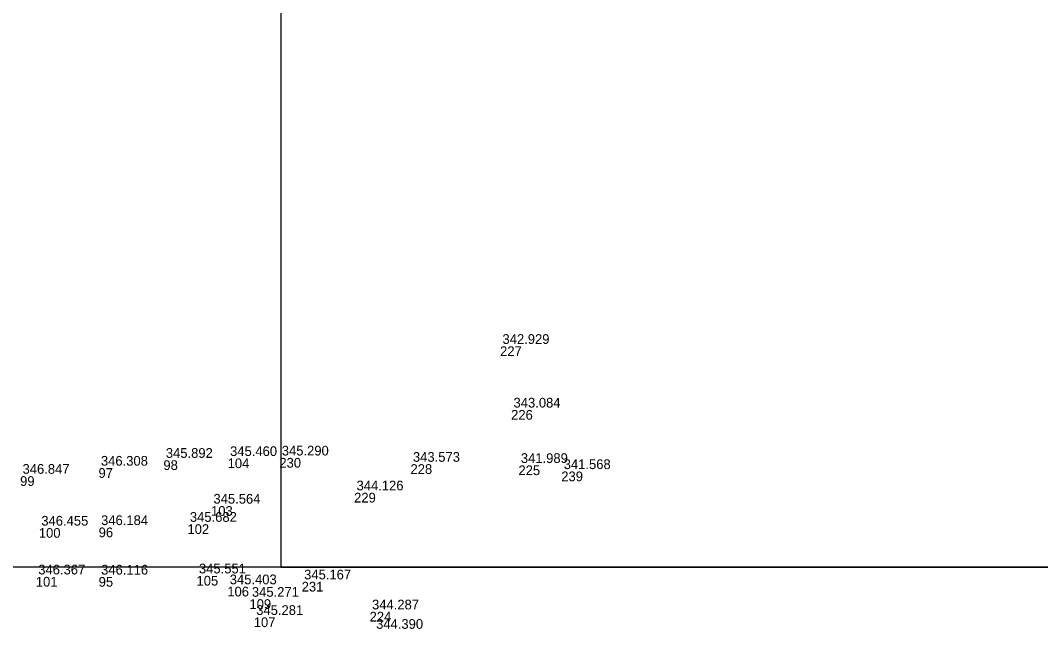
# Model space of a CAD drawing. Extents: x -829398 to -819400, y -1074439 to -1067977.
# Drawn here: x -820132.1 to -820006.2, y -1073007.7 to -1072932.5 of the extents above; entities that cross this region are included whole.
import ezdxf

# ---------------------------------------------------------------- set-up
doc = ezdxf.new("R2010")
doc.units = 0
doc.layers.add('Vrstva 60', color=7, linetype='Continuous')
doc.layers.add('Vrstva 61', color=7, linetype='Continuous')

msp = doc.modelspace()

# ---------------------------------------------------------------- linework, layer by layer
at = {"layer": 'Vrstva 60'}
for p, q in [((-820072.932, -1072972.745), (-820072.932, -1072972.745)), ((-820071.568, -1072980.602), (-820071.568, -1072980.602)), ((-820114.491, -1072986.81), (-820114.491, -1072986.81)), ((-820106.559, -1072986.584), (-820106.559, -1072986.584)), ((-820100.177, -1072986.52), (-820100.177, -1072986.52)), ((-820122.503, -1072987.778), (-820122.503, -1072987.778)), ((-820083.986, -1072987.296), (-820083.986, -1072987.296)), ((-820070.663, -1072987.445), (-820070.663, -1072987.445)), ((-820065.374, -1072988.197), (-820065.374, -1072988.197)), ((-820090.948, -1072990.825), (-820090.948, -1072990.825)), ((-820108.61, -1072992.466), (-820108.61, -1072992.466)), ((-820111.523, -1072994.708), (-820111.523, -1072994.708)), ((-820129.862, -1072995.178), (-820129.862, -1072995.178)), ((-820122.481, -1072995.109), (-820122.481, -1072995.109)), ((-820130.238, -1073001.201), (-820130.238, -1073001.201)), ((-820122.479, -1073001.22), (-820122.479, -1073001.22)), ((-820110.403, -1073001.077), (-820110.403, -1073001.077)), ((-820097.418, -1073001.815), (-820097.418, -1073001.815)), ((-820106.602, -1073002.418), (-820106.602, -1073002.418)), ((-820103.866, -1073003.96), (-820103.866, -1073003.96)), ((-820089.036, -1073005.519), (-820089.036, -1073005.519)), ((-820103.333, -1073006.203), (-820103.333, -1073006.203))]:
    msp.add_line(p, q, dxfattribs=at)
at = {"layer": 'Vrstva 61'}
for points in [[(-819400, -1072500), (-820100, -1072500), (-820100, -1073000), (-819400, -1073000)], [(-819500, -1073000), (-820200, -1073000), (-820200, -1073500), (-819500, -1073500)]]:
    msp.add_lwpolyline(points, close=True, dxfattribs=at)

# ---------------------------------------------------------------- texts
at = {"layer": 'Vrstva 60'}
for s, p in [('227', (-820072.932, -1072973.945)), ('226', (-820071.568, -1072981.802)), ('98', (-820114.491, -1072988.01)), ('104', (-820106.559, -1072987.784)), ('230', (-820100.177, -1072987.72)), ('97', (-820122.503, -1072988.978)), ('228', (-820083.986, -1072988.496)), ('225', (-820070.663, -1072988.645)), ('239', (-820065.374, -1072989.397)), ('99', (-820132.179, -1072989.977)), ('229', (-820090.948, -1072992.025)), ('103', (-820108.61, -1072993.666)), ('102', (-820111.523, -1072995.908)), ('100', (-820129.862, -1072996.378)), ('96', (-820122.481, -1072996.309)), ('101', (-820130.238, -1073002.401)), ('95', (-820122.479, -1073002.42)), ('105', (-820110.403, -1073002.277)), ('231', (-820097.418, -1073003.015)), ('106', (-820106.602, -1073003.618)), ('109', (-820103.866, -1073005.16)), ('224', (-820089.036, -1073006.719)), ('107', (-820103.333, -1073007.403))]:
    msp.add_text(s, height=1.2, dxfattribs=at).set_placement(p)
at = {"layer": 'Vrstva 61'}
for s, p in [('342.929', (-820072.632, -1072972.445)), ('343.084', (-820071.268, -1072980.302)), ('345.892', (-820114.191, -1072986.51)), ('345.460', (-820106.259, -1072986.284)), ('345.290', (-820099.877, -1072986.22)), ('343.573', (-820083.686, -1072986.996)), ('346.308', (-820122.203, -1072987.478)), ('341.989', (-820070.363, -1072987.145)), ('341.568', (-820065.074, -1072987.897)), ('346.847', (-820131.879, -1072988.477)), ('344.126', (-820090.648, -1072990.525)), ('345.564', (-820108.31, -1072992.166)), ('345.682', (-820111.223, -1072994.408)), ('346.455', (-820129.562, -1072994.878)), ('346.184', (-820122.181, -1072994.809)), ('346.367', (-820129.938, -1073000.901)), ('346.116', (-820122.179, -1073000.92)), ('345.551', (-820110.103, -1073000.777)), ('345.403', (-820106.302, -1073002.118)), ('345.167', (-820097.118, -1073001.515)), ('345.271', (-820103.566, -1073003.66)), ('345.281', (-820103.033, -1073005.903)), ('344.287', (-820088.736, -1073005.219)), ('344.390', (-820088.234, -1073007.616))]:
    msp.add_text(s, height=1.2, dxfattribs=at).set_placement(p)

doc.saveas('drawing.dxf')
